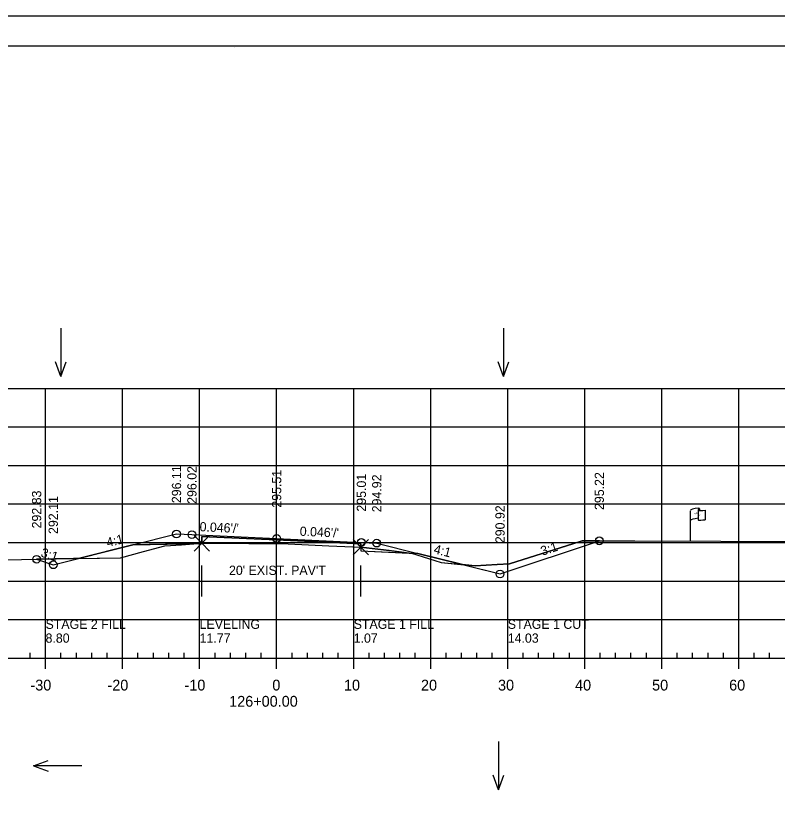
# Model space of a CAD drawing. Extents: x 1370843 to 1371177, y 380307 to 382654.
# Drawn here: x 1370979.8 to 1371078.7, y 382339.3 to 382440.8 of the extents above; entities that cross this region are included whole.
import ezdxf

# ---------------------------------------------------------------- set-up
doc = ezdxf.new("R2010")
doc.units = 0
for name, color, linetype in [('R_Alt Surface', 7, 'Continuous'), ('R_Axis', 7, 'Continuous'), ('R_Axis Annot', 7, 'Continuous'), ('R_Border', 7, 'Continuous'), ('R_Exist Surface', 7, 'Continuous'), ('R_Exist Surface Annot', 7, 'Continuous'), ('R_Fin Surface', 7, 'Continuous'), ('R_Fin Surface Annot', 7, 'Continuous'), ('R_Grid', 7, 'Continuous'), ('R_No Plot', 7, 'Continuous'), ('R_ROW', 7, 'Continuous'), ('R_Water Annot', 7, 'Continuous')]:
    doc.layers.add(name, color=color, linetype=linetype)

msp = doc.modelspace()

# ---------------------------------------------------------------- linework, layer by layer
at = {"layer": 'R_Alt Surface'}
msp.add_lwpolyline([(1370995.06, 382372.19), (1371004.01, 382372.36), (1371004.01, 382373.28), (1371013.71, 382372.84), (1371024.65, 382372.34), (1371024.65, 382371.42), (1371032.02, 382371.08)], dxfattribs=at)
at = {"layer": 'R_Axis'}
for p, q in [((1370981.71, 382357.49), (1370981.71, 382358.19)), ((1370985.71, 382357.49), (1370985.71, 382358.19)), ((1370987.71, 382357.49), (1370987.71, 382358.19)), ((1370989.71, 382357.49), (1370989.71, 382358.19)), ((1370991.71, 382357.49), (1370991.71, 382358.19)), ((1370995.71, 382357.49), (1370995.71, 382358.19)), ((1370997.71, 382357.49), (1370997.71, 382358.19)), ((1370999.71, 382357.49), (1370999.71, 382358.19)), ((1371001.71, 382357.49), (1371001.71, 382358.19)), ((1371005.71, 382357.49), (1371005.71, 382358.19)), ((1371007.71, 382357.49), (1371007.71, 382358.19)), ((1371009.71, 382357.49), (1371009.71, 382358.19)), ((1371011.71, 382357.49), (1371011.71, 382358.19)), ((1371015.71, 382357.49), (1371015.71, 382358.19)), ((1371017.71, 382357.49), (1371017.71, 382358.19)), ((1371019.71, 382357.49), (1371019.71, 382358.19)), ((1371021.71, 382357.49), (1371021.71, 382358.19)), ((1371025.71, 382357.49), (1371025.71, 382358.19)), ((1371027.71, 382357.49), (1371027.71, 382358.19)), ((1371029.71, 382357.49), (1371029.71, 382358.19)), ((1371031.71, 382357.49), (1371031.71, 382358.19)), ((1371035.71, 382357.49), (1371035.71, 382358.19)), ((1371037.71, 382357.49), (1371037.71, 382358.19)), ((1371039.71, 382357.49), (1371039.71, 382358.19)), ((1371041.71, 382357.49), (1371041.71, 382358.19)), ((1371045.71, 382357.49), (1371045.71, 382358.19)), ((1371047.71, 382357.49), (1371047.71, 382358.19)), ((1371049.71, 382357.49), (1371049.71, 382358.19)), ((1371051.71, 382357.49), (1371051.71, 382358.19)), ((1371055.71, 382357.49), (1371055.71, 382358.19)), ((1371057.71, 382357.49), (1371057.71, 382358.19)), ((1371059.71, 382357.49), (1371059.71, 382358.19)), ((1371061.71, 382357.49), (1371061.71, 382358.19)), ((1371065.71, 382357.49), (1371065.71, 382358.19)), ((1371067.71, 382357.49), (1371067.71, 382358.19)), ((1371069.71, 382357.49), (1371069.71, 382358.19)), ((1371071.71, 382357.49), (1371071.71, 382358.19)), ((1371075.71, 382357.49), (1371075.71, 382358.19)), ((1371077.71, 382357.49), (1371077.71, 382358.19)), ((1370868.71, 382357.49), (1371158.71, 382357.49)), ((1370983.71, 382356.09), (1370983.71, 382357.49)), ((1370993.71, 382356.09), (1370993.71, 382357.49)), ((1371003.71, 382356.09), (1371003.71, 382357.49)), ((1371013.71, 382356.09), (1371013.71, 382357.49)), ((1371023.71, 382356.09), (1371023.71, 382357.49)), ((1371033.71, 382356.09), (1371033.71, 382357.49)), ((1371043.71, 382356.09), (1371043.71, 382357.49)), ((1371053.71, 382356.09), (1371053.71, 382357.49)), ((1371063.71, 382356.09), (1371063.71, 382357.49)), ((1371073.71, 382356.09), (1371073.71, 382357.49))]:
    msp.add_line(p, q, dxfattribs=at)
at = {"layer": 'R_Border'}
for p, q in [((1370855.71, 382436.95), (1371171.89, 382436.95)), ((1371008.23, 382436.69), (1371008.23, 382436.69)), ((1371008.23, 382436.69), (1371008.23, 382436.69))]:
    msp.add_line(p, q, dxfattribs=at)
at = {"layer": 'R_Exist Surface'}
msp.add_lwpolyline([(1370961.24, 382370.13), (1370980.58, 382370.28), (1370987.36, 382370.41), (1370993.44, 382370.52), (1370996.44, 382371.33), (1370999.19, 382372.08), (1371001.34, 382372.21), (1371004.01, 382372.39), (1371010.11, 382372.36), (1371015.22, 382372.32), (1371020.5, 382372.07), (1371024.65, 382371.88), (1371028.33, 382371.45), (1371031.23, 382371.1), (1371033.41, 382370.41), (1371035.07, 382369.9), (1371037.6, 382369.65), (1371039.48, 382369.46), (1371042.35, 382369.62), (1371043.93, 382369.72), (1371052.27, 382372.37), (1371053.35, 382372.71), (1371060.22, 382372.7), (1371104.85, 382372.54)], dxfattribs=at)
at = {"layer": 'R_Exist Surface Annot'}
for p, q in [((1371004.01, 382365.49), (1371004.01, 382369.49)), ((1371024.65, 382365.49), (1371024.65, 382369.49)), ((1371004.01, 382367.49), (1371024.65, 382367.49))]:
    msp.add_line(p, q, dxfattribs=at)
at = {"layer": 'R_Fin Surface'}
msp.add_lwpolyline([(1370982.55, 382370.32), (1370984.7, 382369.6), (1370984.71, 382369.6), (1370995.06, 382372.19), (1371000.71, 382373.6), (1371002.71, 382373.51), (1371013.71, 382373.01), (1371024.71, 382372.5), (1371026.71, 382372.41), (1371032.02, 382371.08), (1371042.71, 382368.41), (1371055.6, 382372.71)], dxfattribs=at)
at = {"layer": 'R_Grid'}
for p, q in [((1370868.71, 382392.49), (1371158.71, 382392.49)), ((1370983.71, 382357.49), (1370983.71, 382392.49)), ((1370993.71, 382357.49), (1370993.71, 382392.49)), ((1371003.71, 382357.49), (1371003.71, 382392.49)), ((1371013.71, 382357.49), (1371013.71, 382392.49)), ((1371023.71, 382357.49), (1371023.71, 382392.49)), ((1371033.71, 382357.49), (1371033.71, 382392.49)), ((1371043.71, 382357.49), (1371043.71, 382392.49)), ((1371053.71, 382357.49), (1371053.71, 382392.49)), ((1371063.71, 382357.49), (1371063.71, 382392.49)), ((1371073.71, 382357.49), (1371073.71, 382392.49)), ((1370868.71, 382387.49), (1371158.71, 382387.49)), ((1370868.71, 382382.49), (1371158.71, 382382.49)), ((1370868.71, 382377.49), (1371158.71, 382377.49)), ((1370868.71, 382372.49), (1371158.71, 382372.49)), ((1370868.71, 382367.49), (1371158.71, 382367.49)), ((1370868.71, 382362.49), (1371158.71, 382362.49)), ((1370868.71, 382357.49), (1371158.71, 382357.49))]:
    msp.add_line(p, q, dxfattribs=at)
at = {"layer": 'R_No Plot'}
msp.add_line((1370843.31, 382440.84), (1371176.64, 382440.84), dxfattribs=at)
for points in [[(1370843.3, 382440.84), (1371176.64, 382440.84), (1371176.64, 382227.51), (1370843.3, 382227.51)], [(1371089.63, 382436.95), (1371089.63, 382427.07), (1371125.36, 382427.07), (1371125.36, 382424.15), (1371148.56, 382424.15), (1371148.56, 382399.82), (1371171.89, 382399.82), (1371171.89, 382231.49), (1370855.71, 382231.49), (1370855.71, 382436.95)], [(1371004.01, 382372.39), (1371010.11, 382372.36), (1371015.22, 382372.32), (1371020.5, 382372.07), (1371024.65, 382371.88), (1371024.65, 382372.34), (1371013.71, 382372.84), (1371004.01, 382373.28)], [(1370988.01, 382370.42), (1370993.44, 382370.52), (1370996.44, 382371.33), (1370999.19, 382372.08), (1371001.34, 382372.21), (1371003.49, 382372.35), (1370995.06, 382372.19)], [(1371004.01, 382372.39), (1371004.01, 382372.36), (1371003.49, 382372.35)], [(1371037.83, 382369.63), (1371042.71, 382368.41), (1371055.64, 382372.71), (1371053.35, 382372.71), (1371052.27, 382372.37), (1371043.93, 382369.72), (1371042.35, 382369.62), (1371039.48, 382369.46)], [(1371024.65, 382371.88), (1371024.65, 382371.42), (1371030.92, 382371.13), (1371028.33, 382371.45)], [(1370982.55, 382370.32), (1370984.71, 382369.6), (1370988.01, 382370.42), (1370987.36, 382370.41)], [(1371030.92, 382371.13), (1371031.23, 382371.1), (1371033.41, 382370.41), (1371035.07, 382369.9), (1371037.83, 382369.63), (1371032.02, 382371.08)]]:
    msp.add_lwpolyline(points, close=True, dxfattribs=at)
for points in [[(1371004.01, 382372.39), (1371003.01, 382373.39), (1371004.01, 382372.39), (1371003.01, 382371.39), (1371004.01, 382372.39), (1371005.01, 382371.39), (1371004.01, 382372.39), (1371005.01, 382373.39)], [(1371024.65, 382371.88), (1371023.65, 382372.88), (1371024.65, 382371.88), (1371023.65, 382370.88), (1371024.65, 382371.88), (1371025.65, 382370.88), (1371024.65, 382371.88), (1371025.65, 382372.88)]]:
    msp.add_lwpolyline(points, dxfattribs=at)
for centre in [(1371000.71, 382373.6), (1371002.71, 382373.51), (1371013.71, 382373.01), (1371024.71, 382372.5), (1371026.71, 382372.41), (1371055.6, 382372.71), (1370982.55, 382370.32), (1370984.71, 382369.6), (1371042.71, 382368.41)]:
    msp.add_circle(centre, 0.5, dxfattribs=at)
at = {"layer": 'R_ROW'}
for p, q in [((1371067.42, 382372.67), (1371067.42, 382376.62)), ((1371068.42, 382376.72), (1371068.42, 382376.7)), ((1371068.42, 382376.7), (1371068.42, 382375.48)), ((1371068.59, 382376.87), (1371068.59, 382376.63)), ((1371069.35, 382376.68), (1371069.35, 382375.44))]:
    msp.add_line(p, q, dxfattribs=at)
for centre, radius, start, end in [((1371068.5, 382376.72), 0.078, 88.6458, 274.2828), ((1371068.51, 382376.87), 0.0783, 263.0712, 93.9564), ((1371068.5, 382375.48), 0.0783, 180, 273.9564)]:
    msp.add_arc(centre, radius, start, end, dxfattribs=at)
for centre, major_axis, ratio, start_param, end_param in [((1371069, 382376.67), (-1.58, -0.04), 0.19887, 5.030368, 6.283185), ((1371069.71, 382376.78), (-1.23, -0.13), 0.052933, 0.159456, 1.268315), ((1371069, 382375.35), (-1.58, -0.04), 0.19887, 5.083035, 6.194897), ((1371069.71, 382375.54), (-1.23, -0.13), 0.052933, 0.159456, 1.268315)]:
    msp.add_ellipse(centre, major_axis=major_axis, ratio=ratio, start_param=start_param, end_param=end_param, dxfattribs=at)
at = {"layer": 'R_Water Annot'}
for p, q in [((1370985.7, 382400.31), (1370985.7, 382394.02)), ((1371043.15, 382400.31), (1371043.15, 382394.02)), ((1370985.7, 382394.02), (1370985, 382395.95)), ((1370985.7, 382394.02), (1370986.4, 382395.95)), ((1371043.15, 382394.02), (1371042.45, 382395.95)), ((1371043.15, 382394.02), (1371043.85, 382395.95)), ((1371042.51, 382346.67), (1371042.51, 382340.39)), ((1370982.13, 382343.53), (1370984.05, 382344.23)), ((1370988.41, 382343.53), (1370982.13, 382343.53)), ((1370982.13, 382343.53), (1370984.05, 382342.83)), ((1371042.51, 382340.39), (1371041.81, 382342.31)), ((1371042.51, 382340.39), (1371043.21, 382342.31))]:
    msp.add_line(p, q, dxfattribs=at)

# ---------------------------------------------------------------- texts
at = {"layer": 'R_Axis Annot'}
for s, p in [('-30', (1370981.75, 382353.29)), ('-20', (1370991.75, 382353.29)), ('-10', (1371001.75, 382353.29)), ('0', (1371013.15, 382353.29)), ('10', (1371022.45, 382353.29)), ('20', (1371032.45, 382353.29)), ('30', (1371042.45, 382353.29)), ('40', (1371052.45, 382353.29)), ('50', (1371062.45, 382353.29)), ('60', (1371072.45, 382353.29)), ('126+00.00', (1371007.55, 382351.19))]:
    msp.add_text(s, height=1.4, dxfattribs=at).set_placement(p)
at = {"layer": 'R_Exist Surface Annot'}
msp.add_text("20' EXIST. PAV'T", height=1.2, dxfattribs=at).set_placement((1371007.53, 382368.29))
at = {"layer": 'R_Fin Surface Annot'}
for s, rotation, p in [('296.11', 90, (1371001.31, 382377.6)), ('296.02', 90, (1371003.31, 382377.51)), ('295.51', 90, (1371014.31, 382377.01)), ('295.22', 90, (1371056.2, 382376.71)), ('295.01', 90, (1371025.31, 382376.5)), ('294.92', 90, (1371027.31, 382376.41)), ('292.83', 90, (1370983.15, 382374.32)), ('292.11', 90, (1370985.31, 382373.6)), ('290.92', 90, (1371043.31, 382372.41)), ("0.046'/'", 357.3826, (1371003.69, 382373.96)), ("0.046'/'", 357.3826, (1371016.69, 382373.37)), ('4:1', 14.0362, (1370991.78, 382371.88)), ('3:1', 18.4349, (1371048.21, 382370.77)), ('3:1', 341.5651, (1370983, 382370.7)), ('4:1', 345.9638, (1371034.02, 382371.1))]:
    msp.add_text(s, height=1.2, rotation=rotation, dxfattribs=at).set_placement(p)
at = {"layer": 'R_No Plot'}
for s, p in [('STAGE 2 FILL', (1370983.71, 382361.29)), ('LEVELING', (1371003.71, 382361.29)), ('STAGE 1 FILL', (1371023.71, 382361.29)), ('STAGE 1 CUT', (1371043.71, 382361.29)), ('8.80', (1370983.71, 382359.49)), ('11.77', (1371003.71, 382359.49)), ('1.07', (1371023.71, 382359.49)), ('14.03', (1371043.71, 382359.49))]:
    msp.add_text(s, height=1.2, dxfattribs=at).set_placement(p)
at = {"layer": 'R_ROW'}
for s, height, rotation, p in [('R ', 0.2, 9.9884, (1371067.94, 382376.12)), (' O', 0.2, 9.9884, (1371068.09, 382376.17)), ('DWB 11-9-07', 0.001, 90, (1371068.59, 382376.63)), ('W', 0.2, 351.1788, (1371068.42, 382376)), ('DWB 11-9-07', 0.001, 5.0717, (1371069.34, 382375.44)), ('DWB 11-9-07', 0.001, 90, (1371067.42, 382372.67))]:
    msp.add_text(s, height=height, rotation=rotation, dxfattribs=at).set_placement(p)

doc.saveas('drawing.dxf')
